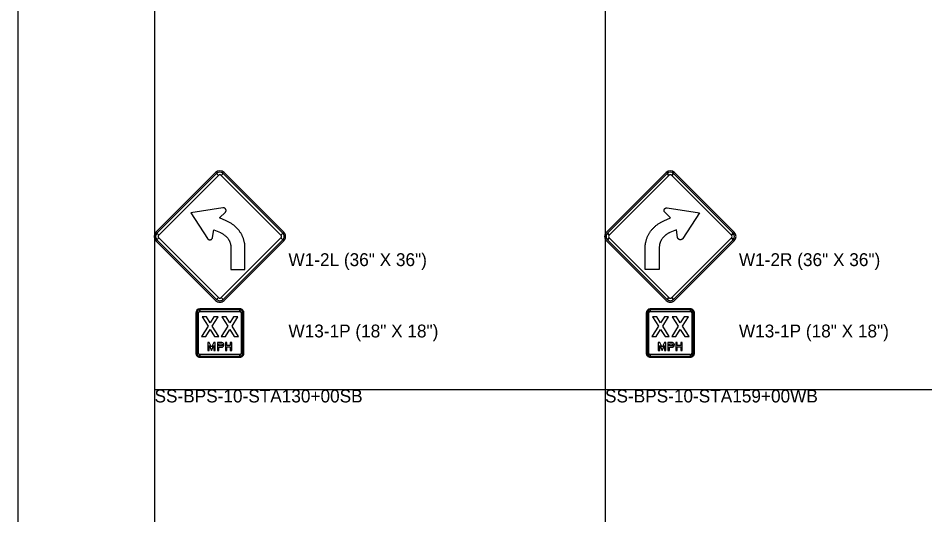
# Model space of a CAD drawing. Extents: x 1001568 to 1002149, y 1840825 to 1841423.
# Drawn here: x 1001886.41 to 1001914.59, y 1841063.57 to 1841079.02 of the extents above; entities that cross this region are included whole.
import ezdxf

# ---------------------------------------------------------------- set-up
doc = ezdxf.new("R2010")
doc.units = 0
for name, color, linetype in [('40', 7, 'Continuous'), ('R_No Plot', 7, 'Continuous'), ('SIGNS', 7, 'Continuous')]:
    doc.layers.add(name, color=color, linetype=linetype)

msp = doc.modelspace()

# ---------------------------------------------------------------- linework, layer by layer
at = {"layer": 'R_No Plot'}
for p, q in [((1001890.65, 1841110.667), (1001890.65, 1841048.127)), ((1001904.65, 1841110.667), (1001904.65, 1841048.127)), ((1001890.65, 1841067.469), (1001982.133, 1841067.469))]:
    msp.add_line(p, q, dxfattribs=at)
msp.add_lwpolyline([(1001886.411, 1841110.667), (1001964.232, 1841110.667), (1001964.232, 1841107.694), (1001968.454, 1841107.694), (1001968.454, 1841106.882), (1001982.133, 1841106.882), (1001982.133, 1841048.127), (1001886.411, 1841048.127)], close=True, dxfattribs=at)
at = {"layer": 'SIGNS'}
for p, q in [((1001890.691, 1841072.362), (1001892.547, 1841074.218)), ((1001892.636, 1841074.13), (1001892.58, 1841074.185)), ((1001892.779, 1841074.185), (1001892.724, 1841074.13)), ((1001892.812, 1841074.218), (1001894.668, 1841072.362)), ((1001906.547, 1841074.218), (1001904.691, 1841072.362)), ((1001906.58, 1841074.185), (1001906.636, 1841074.13)), ((1001906.724, 1841074.13), (1001906.779, 1841074.185)), ((1001908.668, 1841072.362), (1001906.812, 1841074.218)), ((1001892.774, 1841073.119), (1001891.773, 1841072.967)), ((1001891.773, 1841072.967), (1001892.294, 1841072.165)), ((1001892.672, 1841072.805), (1001892.852, 1841072.988)), ((1001906.688, 1841072.805), (1001906.508, 1841072.988)), ((1001906.585, 1841073.119), (1001907.586, 1841072.967)), ((1001907.586, 1841072.967), (1001907.065, 1841072.165)), ((1001892.881, 1841072.716), (1001892.672, 1841072.805)), ((1001892.902, 1841072.707), (1001892.881, 1841072.716)), ((1001906.457, 1841072.707), (1001906.478, 1841072.716)), ((1001906.478, 1841072.716), (1001906.688, 1841072.805)), ((1001890.724, 1841072.329), (1001890.779, 1841072.274)), ((1001892.453, 1841072.196), (1001892.488, 1841072.44)), ((1001892.488, 1841072.44), (1001892.697, 1841072.35)), ((1001892.697, 1841072.35), (1001892.713, 1841072.344)), ((1001894.58, 1841072.274), (1001894.635, 1841072.329)), ((1001904.779, 1841072.274), (1001904.724, 1841072.329)), ((1001906.662, 1841072.35), (1001906.647, 1841072.344)), ((1001906.872, 1841072.44), (1001906.662, 1841072.35)), ((1001906.907, 1841072.196), (1001906.872, 1841072.44)), ((1001908.635, 1841072.329), (1001908.58, 1841072.274)), ((1001892.547, 1841070.241), (1001890.691, 1841072.097)), ((1001890.779, 1841072.185), (1001890.724, 1841072.13)), ((1001894.668, 1841072.097), (1001892.812, 1841070.241)), ((1001894.635, 1841072.13), (1001894.58, 1841072.185)), ((1001904.691, 1841072.097), (1001906.547, 1841070.241)), ((1001904.724, 1841072.13), (1001904.779, 1841072.185)), ((1001906.812, 1841070.241), (1001908.668, 1841072.097)), ((1001908.58, 1841072.185), (1001908.635, 1841072.13)), ((1001893.024, 1841071.881), (1001893.024, 1841071.202)), ((1001893.461, 1841071.202), (1001893.461, 1841071.881)), ((1001905.898, 1841071.202), (1001905.898, 1841071.881)), ((1001906.336, 1841071.881), (1001906.336, 1841071.202)), ((1001893.024, 1841071.202), (1001893.461, 1841071.202)), ((1001906.336, 1841071.202), (1001905.898, 1841071.202)), ((1001892.58, 1841070.274), (1001892.636, 1841070.329)), ((1001892.724, 1841070.329), (1001892.779, 1841070.274)), ((1001906.636, 1841070.329), (1001906.58, 1841070.274)), ((1001906.779, 1841070.274), (1001906.724, 1841070.329)), ((1001891.93, 1841069.853), (1001891.93, 1841068.603)), ((1001891.961, 1841069.853), (1001892.013, 1841069.853)), ((1001893.305, 1841069.978), (1001892.055, 1841069.978)), ((1001892.055, 1841069.894), (1001892.055, 1841069.946)), ((1001893.305, 1841069.946), (1001893.305, 1841069.894)), ((1001893.346, 1841069.853), (1001893.398, 1841069.853)), ((1001893.43, 1841068.603), (1001893.43, 1841069.853)), ((1001905.93, 1841069.853), (1001905.93, 1841068.603)), ((1001905.961, 1841069.853), (1001906.013, 1841069.853)), ((1001907.305, 1841069.978), (1001906.055, 1841069.978)), ((1001906.055, 1841069.894), (1001906.055, 1841069.946)), ((1001907.305, 1841069.946), (1001907.305, 1841069.894)), ((1001907.346, 1841069.853), (1001907.398, 1841069.853)), ((1001907.43, 1841068.603), (1001907.43, 1841069.853)), ((1001892.013, 1841068.603), (1001891.961, 1841068.603)), ((1001892.055, 1841068.509), (1001892.055, 1841068.561)), ((1001892.055, 1841068.478), (1001893.305, 1841068.478)), ((1001893.305, 1841068.561), (1001893.305, 1841068.509)), ((1001893.398, 1841068.603), (1001893.346, 1841068.603)), ((1001906.013, 1841068.603), (1001905.961, 1841068.603)), ((1001906.055, 1841068.509), (1001906.055, 1841068.561)), ((1001906.055, 1841068.478), (1001907.305, 1841068.478)), ((1001907.305, 1841068.561), (1001907.305, 1841068.509)), ((1001907.398, 1841068.603), (1001907.346, 1841068.603))]:
    msp.add_line(p, q, dxfattribs=at)
for points in [[(1001890.724, 1841072.329), (1001892.58, 1841074.185), (1001892.636, 1841074.13), (1001890.779, 1841072.274), (1001890.724, 1841072.329), (1001890.724, 1841072.329)], [(1001892.779, 1841074.185), (1001894.635, 1841072.329), (1001894.58, 1841072.274), (1001892.724, 1841074.13), (1001892.779, 1841074.185), (1001892.779, 1841074.185)], [(1001906.58, 1841074.185), (1001904.724, 1841072.329), (1001904.779, 1841072.274), (1001906.636, 1841074.13), (1001906.58, 1841074.185), (1001906.58, 1841074.185)], [(1001908.635, 1841072.329), (1001906.779, 1841074.185), (1001906.724, 1841074.13), (1001908.58, 1841072.274), (1001908.635, 1841072.329), (1001908.635, 1841072.329)], [(1001892.58, 1841070.274), (1001890.724, 1841072.13), (1001890.779, 1841072.185), (1001892.636, 1841070.329), (1001892.58, 1841070.274), (1001892.58, 1841070.274)], [(1001894.635, 1841072.13), (1001892.779, 1841070.274), (1001892.724, 1841070.329), (1001894.58, 1841072.185), (1001894.635, 1841072.13), (1001894.635, 1841072.13)], [(1001904.724, 1841072.13), (1001906.58, 1841070.274), (1001906.636, 1841070.329), (1001904.779, 1841072.185), (1001904.724, 1841072.13), (1001904.724, 1841072.13)], [(1001906.779, 1841070.274), (1001908.635, 1841072.13), (1001908.58, 1841072.185), (1001906.724, 1841070.329), (1001906.779, 1841070.274), (1001906.779, 1841070.274)], [(1001891.961, 1841069.853), (1001891.961, 1841068.603), (1001892.013, 1841068.603), (1001892.013, 1841069.853), (1001891.961, 1841069.853), (1001891.961, 1841069.853)], [(1001893.305, 1841069.946), (1001892.055, 1841069.946), (1001892.055, 1841069.894), (1001893.305, 1841069.894), (1001893.305, 1841069.946), (1001893.305, 1841069.946)], [(1001893.398, 1841068.603), (1001893.398, 1841069.853), (1001893.346, 1841069.853), (1001893.346, 1841068.603), (1001893.398, 1841068.603), (1001893.398, 1841068.603)], [(1001905.961, 1841069.853), (1001905.961, 1841068.603), (1001906.013, 1841068.603), (1001906.013, 1841069.853), (1001905.961, 1841069.853), (1001905.961, 1841069.853)], [(1001907.305, 1841069.946), (1001906.055, 1841069.946), (1001906.055, 1841069.894), (1001907.305, 1841069.894), (1001907.305, 1841069.946), (1001907.305, 1841069.946)], [(1001907.398, 1841068.603), (1001907.398, 1841069.853), (1001907.346, 1841069.853), (1001907.346, 1841068.603), (1001907.398, 1841068.603), (1001907.398, 1841068.603)], [(1001892.11, 1841069.117), (1001892.24, 1841069.117), (1001892.377, 1841069.338), (1001892.516, 1841069.117), (1001892.647, 1841069.117), (1001892.445, 1841069.441), (1001892.627, 1841069.73), (1001892.495, 1841069.73), (1001892.377, 1841069.548), (1001892.26, 1841069.73), (1001892.127, 1841069.73), (1001892.312, 1841069.441)], [(1001892.723, 1841069.117), (1001892.853, 1841069.117), (1001892.99, 1841069.338), (1001893.129, 1841069.117), (1001893.261, 1841069.117), (1001893.058, 1841069.441), (1001893.241, 1841069.73), (1001893.108, 1841069.73), (1001892.99, 1841069.548), (1001892.873, 1841069.73), (1001892.74, 1841069.73), (1001892.925, 1841069.441)], [(1001906.11, 1841069.117), (1001906.24, 1841069.117), (1001906.377, 1841069.338), (1001906.516, 1841069.117), (1001906.647, 1841069.117), (1001906.445, 1841069.441), (1001906.627, 1841069.73), (1001906.495, 1841069.73), (1001906.377, 1841069.548), (1001906.26, 1841069.73), (1001906.127, 1841069.73), (1001906.312, 1841069.441)], [(1001906.723, 1841069.117), (1001906.853, 1841069.117), (1001906.99, 1841069.338), (1001907.129, 1841069.117), (1001907.261, 1841069.117), (1001907.058, 1841069.441), (1001907.241, 1841069.73), (1001907.108, 1841069.73), (1001906.99, 1841069.548), (1001906.873, 1841069.73), (1001906.74, 1841069.73), (1001906.925, 1841069.441)], [(1001892.306, 1841068.686), (1001892.349, 1841068.686), (1001892.349, 1841068.837), (1001892.421, 1841068.686), (1001892.495, 1841068.837), (1001892.495, 1841068.686), (1001892.538, 1841068.686), (1001892.538, 1841068.931), (1001892.495, 1841068.931), (1001892.421, 1841068.786), (1001892.349, 1841068.931), (1001892.306, 1841068.931)], [(1001892.851, 1841068.686), (1001892.894, 1841068.686), (1001892.894, 1841068.794), (1001893.005, 1841068.794), (1001893.005, 1841068.686), (1001893.051, 1841068.686), (1001893.051, 1841068.931), (1001893.005, 1841068.931), (1001893.005, 1841068.838), (1001892.894, 1841068.838), (1001892.894, 1841068.931), (1001892.851, 1841068.931)], [(1001906.306, 1841068.686), (1001906.349, 1841068.686), (1001906.349, 1841068.837), (1001906.421, 1841068.686), (1001906.495, 1841068.837), (1001906.495, 1841068.686), (1001906.538, 1841068.686), (1001906.538, 1841068.931), (1001906.495, 1841068.931), (1001906.421, 1841068.786), (1001906.349, 1841068.931), (1001906.306, 1841068.931)], [(1001906.851, 1841068.686), (1001906.894, 1841068.686), (1001906.894, 1841068.794), (1001907.005, 1841068.794), (1001907.005, 1841068.686), (1001907.051, 1841068.686), (1001907.051, 1841068.931), (1001907.005, 1841068.931), (1001907.005, 1841068.838), (1001906.894, 1841068.838), (1001906.894, 1841068.931), (1001906.851, 1841068.931)], [(1001892.055, 1841068.509), (1001893.305, 1841068.509), (1001893.305, 1841068.561), (1001892.055, 1841068.561), (1001892.055, 1841068.509), (1001892.055, 1841068.509)], [(1001906.055, 1841068.509), (1001907.305, 1841068.509), (1001907.305, 1841068.561), (1001906.055, 1841068.561), (1001906.055, 1841068.509), (1001906.055, 1841068.509)]]:
    msp.add_lwpolyline(points, close=True, dxfattribs=at)
for points in [[(1001892.852, 1841072.988), (1001892.856, 1841072.992), (1001892.86, 1841072.997), (1001892.863, 1841073.002), (1001892.867, 1841073.008), (1001892.869, 1841073.014), (1001892.871, 1841073.019), (1001892.872, 1841073.025), (1001892.874, 1841073.031), (1001892.874, 1841073.038), (1001892.874, 1841073.044), (1001892.874, 1841073.05), (1001892.873, 1841073.056), (1001892.871, 1841073.062), (1001892.869, 1841073.068), (1001892.867, 1841073.073), (1001892.864, 1841073.079), (1001892.86, 1841073.084), (1001892.856, 1841073.089), (1001892.852, 1841073.094), (1001892.848, 1841073.098), (1001892.842, 1841073.102), (1001892.837, 1841073.106), (1001892.832, 1841073.109), (1001892.826, 1841073.112), (1001892.82, 1841073.114), (1001892.814, 1841073.116), (1001892.807, 1841073.118), (1001892.801, 1841073.119), (1001892.794, 1841073.12), (1001892.787, 1841073.12), (1001892.781, 1841073.12), (1001892.774, 1841073.119)], [(1001906.508, 1841072.988), (1001906.503, 1841072.992), (1001906.499, 1841072.997), (1001906.496, 1841073.002), (1001906.493, 1841073.008), (1001906.49, 1841073.014), (1001906.489, 1841073.019), (1001906.487, 1841073.025), (1001906.486, 1841073.031), (1001906.485, 1841073.038), (1001906.485, 1841073.044), (1001906.486, 1841073.05), (1001906.487, 1841073.056), (1001906.488, 1841073.062), (1001906.49, 1841073.068), (1001906.493, 1841073.073), (1001906.496, 1841073.079), (1001906.499, 1841073.084), (1001906.503, 1841073.089), (1001906.507, 1841073.094), (1001906.512, 1841073.098), (1001906.517, 1841073.102), (1001906.522, 1841073.106), (1001906.528, 1841073.109), (1001906.534, 1841073.112), (1001906.54, 1841073.114), (1001906.546, 1841073.116), (1001906.552, 1841073.118), (1001906.559, 1841073.119), (1001906.565, 1841073.12), (1001906.572, 1841073.12), (1001906.578, 1841073.12), (1001906.585, 1841073.119)], [(1001893.461, 1841071.881), (1001893.461, 1841071.902), (1001893.46, 1841071.923), (1001893.459, 1841071.944), (1001893.457, 1841071.965), (1001893.454, 1841071.985), (1001893.452, 1841072.006), (1001893.448, 1841072.027), (1001893.445, 1841072.047), (1001893.44, 1841072.068), (1001893.435, 1841072.088), (1001893.43, 1841072.109), (1001893.424, 1841072.129), (1001893.418, 1841072.149), (1001893.411, 1841072.169), (1001893.403, 1841072.189), (1001893.396, 1841072.208), (1001893.387, 1841072.228), (1001893.378, 1841072.247), (1001893.369, 1841072.266), (1001893.359, 1841072.285), (1001893.349, 1841072.304), (1001893.338, 1841072.322), (1001893.327, 1841072.341), (1001893.316, 1841072.358), (1001893.304, 1841072.376), (1001893.291, 1841072.394), (1001893.278, 1841072.411), (1001893.265, 1841072.428), (1001893.252, 1841072.445), (1001893.237, 1841072.461), (1001893.223, 1841072.477), (1001893.208, 1841072.493), (1001893.192, 1841072.508), (1001893.177, 1841072.524), (1001893.161, 1841072.538), (1001893.144, 1841072.553), (1001893.127, 1841072.567), (1001893.11, 1841072.581), (1001893.093, 1841072.594), (1001893.075, 1841072.607), (1001893.057, 1841072.62), (1001893.039, 1841072.632), (1001893.02, 1841072.644), (1001893.001, 1841072.655), (1001892.982, 1841072.666), (1001892.962, 1841072.677), (1001892.942, 1841072.687), (1001892.922, 1841072.697), (1001892.902, 1841072.707)], [(1001905.898, 1841071.881), (1001905.899, 1841071.902), (1001905.899, 1841071.923), (1001905.901, 1841071.944), (1001905.902, 1841071.965), (1001905.905, 1841071.985), (1001905.908, 1841072.006), (1001905.911, 1841072.027), (1001905.915, 1841072.047), (1001905.919, 1841072.068), (1001905.924, 1841072.088), (1001905.93, 1841072.109), (1001905.935, 1841072.129), (1001905.942, 1841072.149), (1001905.949, 1841072.169), (1001905.956, 1841072.189), (1001905.964, 1841072.208), (1001905.972, 1841072.228), (1001905.981, 1841072.247), (1001905.99, 1841072.266), (1001906, 1841072.285), (1001906.01, 1841072.304), (1001906.021, 1841072.322), (1001906.032, 1841072.341), (1001906.044, 1841072.358), (1001906.056, 1841072.376), (1001906.068, 1841072.394), (1001906.081, 1841072.411), (1001906.094, 1841072.428), (1001906.108, 1841072.445), (1001906.122, 1841072.461), (1001906.137, 1841072.477), (1001906.152, 1841072.493), (1001906.167, 1841072.508), (1001906.183, 1841072.524), (1001906.199, 1841072.538), (1001906.215, 1841072.553), (1001906.232, 1841072.567), (1001906.249, 1841072.581), (1001906.267, 1841072.594), (1001906.284, 1841072.607), (1001906.302, 1841072.62), (1001906.321, 1841072.632), (1001906.339, 1841072.644), (1001906.359, 1841072.655), (1001906.378, 1841072.666), (1001906.397, 1841072.677), (1001906.417, 1841072.687), (1001906.437, 1841072.697), (1001906.457, 1841072.707)], [(1001892.713, 1841072.344), (1001892.728, 1841072.337), (1001892.742, 1841072.329), (1001892.757, 1841072.321), (1001892.771, 1841072.313), (1001892.785, 1841072.304), (1001892.798, 1841072.295), (1001892.812, 1841072.286), (1001892.825, 1841072.276), (1001892.837, 1841072.265), (1001892.85, 1841072.255), (1001892.862, 1841072.244), (1001892.873, 1841072.233), (1001892.885, 1841072.222), (1001892.895, 1841072.21), (1001892.906, 1841072.197), (1001892.916, 1841072.185), (1001892.926, 1841072.173), (1001892.935, 1841072.159), (1001892.944, 1841072.146), (1001892.952, 1841072.133), (1001892.96, 1841072.119), (1001892.968, 1841072.106), (1001892.975, 1841072.091), (1001892.981, 1841072.077), (1001892.988, 1841072.063), (1001892.993, 1841072.048), (1001892.998, 1841072.033), (1001893.003, 1841072.019), (1001893.008, 1841072.004), (1001893.011, 1841071.989), (1001893.014, 1841071.973), (1001893.017, 1841071.958), (1001893.02, 1841071.943), (1001893.021, 1841071.927), (1001893.022, 1841071.912), (1001893.023, 1841071.897), (1001893.024, 1841071.881)], [(1001906.647, 1841072.344), (1001906.632, 1841072.337), (1001906.617, 1841072.329), (1001906.603, 1841072.321), (1001906.588, 1841072.313), (1001906.574, 1841072.304), (1001906.561, 1841072.295), (1001906.548, 1841072.286), (1001906.535, 1841072.276), (1001906.522, 1841072.265), (1001906.51, 1841072.255), (1001906.498, 1841072.244), (1001906.486, 1841072.233), (1001906.475, 1841072.222), (1001906.464, 1841072.21), (1001906.453, 1841072.197), (1001906.443, 1841072.185), (1001906.434, 1841072.173), (1001906.425, 1841072.159), (1001906.416, 1841072.146), (1001906.407, 1841072.133), (1001906.399, 1841072.119), (1001906.392, 1841072.106), (1001906.384, 1841072.091), (1001906.378, 1841072.077), (1001906.372, 1841072.063), (1001906.366, 1841072.048), (1001906.361, 1841072.033), (1001906.356, 1841072.019), (1001906.352, 1841072.004), (1001906.348, 1841071.989), (1001906.345, 1841071.973), (1001906.342, 1841071.958), (1001906.34, 1841071.943), (1001906.338, 1841071.927), (1001906.337, 1841071.912), (1001906.336, 1841071.897), (1001906.336, 1841071.881)], [(1001892.294, 1841072.165), (1001892.298, 1841072.16), (1001892.302, 1841072.156), (1001892.306, 1841072.151), (1001892.311, 1841072.147), (1001892.316, 1841072.143), (1001892.321, 1841072.139), (1001892.327, 1841072.136), (1001892.333, 1841072.133), (1001892.339, 1841072.131), (1001892.346, 1841072.129), (1001892.352, 1841072.128), (1001892.359, 1841072.127), (1001892.365, 1841072.127), (1001892.372, 1841072.127), (1001892.379, 1841072.127), (1001892.385, 1841072.129), (1001892.392, 1841072.13), (1001892.398, 1841072.132), (1001892.404, 1841072.134), (1001892.41, 1841072.137), (1001892.416, 1841072.14), (1001892.421, 1841072.144), (1001892.426, 1841072.148), (1001892.431, 1841072.152), (1001892.435, 1841072.157), (1001892.439, 1841072.162), (1001892.442, 1841072.167), (1001892.445, 1841072.172), (1001892.448, 1841072.178), (1001892.45, 1841072.184), (1001892.452, 1841072.19), (1001892.453, 1841072.196)], [(1001907.065, 1841072.165), (1001907.062, 1841072.16), (1001907.058, 1841072.156), (1001907.053, 1841072.151), (1001907.048, 1841072.147), (1001907.043, 1841072.143), (1001907.038, 1841072.139), (1001907.032, 1841072.136), (1001907.026, 1841072.133), (1001907.02, 1841072.131), (1001907.014, 1841072.129), (1001907.007, 1841072.128), (1001907.001, 1841072.127), (1001906.994, 1841072.127), (1001906.988, 1841072.127), (1001906.981, 1841072.127), (1001906.974, 1841072.129), (1001906.968, 1841072.13), (1001906.962, 1841072.132), (1001906.955, 1841072.134), (1001906.95, 1841072.137), (1001906.944, 1841072.14), (1001906.939, 1841072.144), (1001906.933, 1841072.148), (1001906.929, 1841072.152), (1001906.924, 1841072.157), (1001906.92, 1841072.162), (1001906.917, 1841072.167), (1001906.914, 1841072.172), (1001906.911, 1841072.178), (1001906.909, 1841072.184), (1001906.907, 1841072.19), (1001906.907, 1841072.196)], [(1001892.606, 1841068.686), (1001892.649, 1841068.686), (1001892.649, 1841068.784), (1001892.721, 1841068.784), (1001892.745, 1841068.786), (1001892.766, 1841068.793), (1001892.782, 1841068.804), (1001892.795, 1841068.821), (1001892.803, 1841068.839), (1001892.806, 1841068.857), (1001892.805, 1841068.873), (1001892.8, 1841068.887), (1001892.793, 1841068.899), (1001892.783, 1841068.91), (1001892.771, 1841068.919), (1001892.757, 1841068.926), (1001892.743, 1841068.93), (1001892.726, 1841068.931), (1001892.606, 1841068.931), (1001892.606, 1841068.686)], [(1001906.606, 1841068.686), (1001906.649, 1841068.686), (1001906.649, 1841068.784), (1001906.721, 1841068.784), (1001906.745, 1841068.786), (1001906.766, 1841068.793), (1001906.782, 1841068.804), (1001906.795, 1841068.821), (1001906.803, 1841068.839), (1001906.806, 1841068.857), (1001906.805, 1841068.873), (1001906.8, 1841068.887), (1001906.793, 1841068.899), (1001906.783, 1841068.91), (1001906.771, 1841068.919), (1001906.757, 1841068.926), (1001906.743, 1841068.93), (1001906.726, 1841068.931), (1001906.606, 1841068.931), (1001906.606, 1841068.686)], [(1001892.649, 1841068.825), (1001892.649, 1841068.888), (1001892.722, 1841068.888), (1001892.737, 1841068.886), (1001892.748, 1841068.88), (1001892.757, 1841068.87), (1001892.76, 1841068.856), (1001892.757, 1841068.844), (1001892.749, 1841068.834), (1001892.738, 1841068.827), (1001892.725, 1841068.825), (1001892.649, 1841068.825)], [(1001906.649, 1841068.825), (1001906.649, 1841068.888), (1001906.722, 1841068.888), (1001906.737, 1841068.886), (1001906.748, 1841068.88), (1001906.757, 1841068.87), (1001906.76, 1841068.856), (1001906.757, 1841068.844), (1001906.749, 1841068.834), (1001906.738, 1841068.827), (1001906.725, 1841068.825), (1001906.649, 1841068.825)]]:
    msp.add_lwpolyline(points, dxfattribs=at)
for centre, radius, start, end in [((1001892.68, 1841074.086), 0.187, 45.0003, 135), ((1001906.68, 1841074.086), 0.187, 45, 134.9997), ((1001892.68, 1841074.086), 0.141, 45.0003, 135), ((1001892.68, 1841074.086), 0.0625, 45.0003, 135), ((1001906.68, 1841074.086), 0.141, 45, 134.9997), ((1001906.68, 1841074.086), 0.0625, 45, 134.9997), ((1001890.824, 1841072.229), 0.187, 135.0002, 224.9998), ((1001890.824, 1841072.229), 0.141, 135.0002, 224.9998), ((1001894.536, 1841072.229), 0.141, 315, 45.0003), ((1001894.536, 1841072.229), 0.187, 315, 45.0003), ((1001904.824, 1841072.229), 0.187, 134.9997, 225), ((1001904.824, 1841072.229), 0.141, 134.9997, 225), ((1001908.536, 1841072.229), 0.141, 315.0002, 44.9998), ((1001908.536, 1841072.229), 0.187, 315.0002, 44.9998), ((1001890.824, 1841072.229), 0.0625, 135.0002, 224.9998), ((1001894.536, 1841072.229), 0.0625, 315, 45.0003), ((1001904.824, 1841072.229), 0.0625, 134.9997, 225), ((1001908.536, 1841072.229), 0.0625, 315.0002, 44.9998), ((1001892.68, 1841070.373), 0.0625, 224.9998, 315), ((1001906.68, 1841070.373), 0.0625, 225, 315.0002), ((1001892.68, 1841070.373), 0.187, 224.9998, 315), ((1001892.68, 1841070.373), 0.141, 224.9998, 315), ((1001906.68, 1841070.373), 0.187, 225, 315.0002), ((1001906.68, 1841070.373), 0.141, 225, 315.0002), ((1001892.055, 1841069.853), 0.125, 90.0002, 179.9998), ((1001892.055, 1841069.853), 0.0937, 90.0002, 179.9998), ((1001892.055, 1841069.853), 0.0417, 90.0002, 179.9998), ((1001893.305, 1841069.853), 0.125, 0, 90.0002), ((1001893.305, 1841069.853), 0.0937, 0, 90.0002), ((1001893.305, 1841069.853), 0.0417, 0, 90.0002), ((1001906.055, 1841069.853), 0.125, 90.0002, 179.9998), ((1001906.055, 1841069.853), 0.0937, 90.0002, 179.9998), ((1001906.055, 1841069.853), 0.0417, 90.0002, 179.9998), ((1001907.305, 1841069.853), 0.125, 0, 90.0002), ((1001907.305, 1841069.853), 0.0937, 0, 90.0002), ((1001907.305, 1841069.853), 0.0417, 0, 90.0002), ((1001892.055, 1841068.603), 0.125, 179.9998, 270.0001), ((1001892.055, 1841068.603), 0.0937, 179.9998, 270.0001), ((1001892.055, 1841068.603), 0.0417, 179.9998, 270.0001), ((1001893.305, 1841068.603), 0.125, 270.0001, 0.0003), ((1001893.305, 1841068.603), 0.0937, 270.0001, 0.0003), ((1001893.305, 1841068.603), 0.0417, 270.0001, 0.0003), ((1001906.055, 1841068.603), 0.125, 179.9998, 270.0001), ((1001906.055, 1841068.603), 0.0937, 179.9998, 270.0001), ((1001906.055, 1841068.603), 0.0417, 179.9998, 270.0001), ((1001907.305, 1841068.603), 0.125, 270.0001, 0.0003), ((1001907.305, 1841068.603), 0.0937, 270.0001, 0.0003), ((1001907.305, 1841068.603), 0.0417, 270.0001, 0.0003)]:
    msp.add_arc(centre, radius, start, end, dxfattribs=at)

# ---------------------------------------------------------------- texts
at = {"layer": '40'}
for s, p in [('W1-2L (36" X 36")', (1001894.811, 1841071.309)), ('W1-2R (36" X 36")', (1001908.811, 1841071.309)), ('W13-1P (18" X 18")', (1001894.811, 1841069.091)), ('W13-1P (18" X 18")', (1001908.811, 1841069.091)), ('SS-BPS-10-STA130+00SB', (1001890.65, 1841067.069)), ('SS-BPS-10-STA159+00WB', (1001904.65, 1841067.069))]:
    msp.add_text(s, height=0.4, rotation=0, dxfattribs=at).set_placement(p)

doc.saveas('drawing.dxf')
